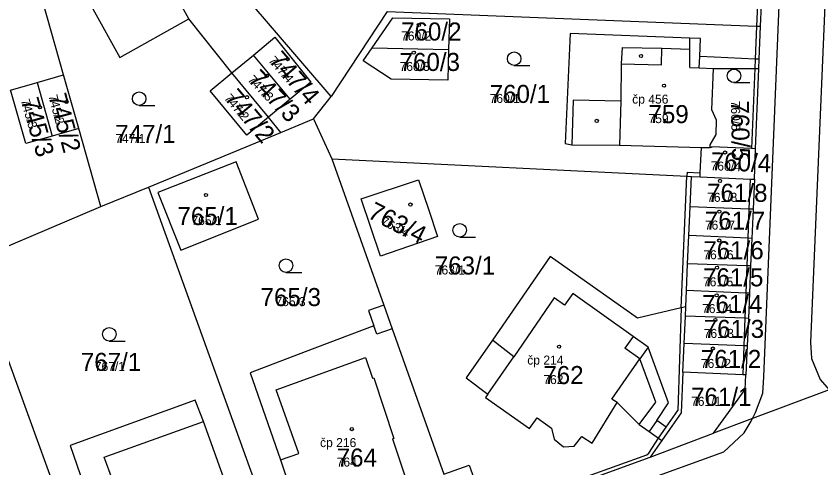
# Model space of a CAD drawing. Extents: x -763628 to -761565, y -976033 to -973833.
# Drawn here: x -762257.5 to -762168.3, y -974769.9 to -974719.9 of the extents above; entities that cross this region are included whole.
import ezdxf

# ---------------------------------------------------------------- set-up
doc = ezdxf.new("R2010")
doc.units = 0
for name, color, linetype in [('KN_cisla parcel 1000', 7, 'Continuous'), ('KN_cisla parcel 500', 7, 'Continuous'), ('KN_cisla popisna 500', 7, 'Continuous'), ('KN_hranice parcel', 7, 'Continuous'), ('KN_vnitrni kresba parcel', 7, 'Continuous'), ('KN_znacky budov', 7, 'Continuous'), ('KN_znacky kultur', 7, 'Continuous')]:
    doc.layers.add(name, color=color, linetype=linetype)

msp = doc.modelspace()

# ---------------------------------------------------------------- linework, layer by layer
at = {"layer": 'KN_hranice parcel'}
for p, q in [((-762222.55, -974728.78), (-762232.18, -974717.57)), ((-762174.98, -974721.01), (-762174.88, -974718.63)), ((-762216.37, -974719.37), (-762222.55, -974728.78)), ((-762175.13, -974724.67), (-762174.98, -974721.01)), ((-762233.58, -974726.19), (-762231.17, -974724.2)), ((-762227.11, -974729.1), (-762231.17, -974724.2)), ((-762218.03, -974723.4), (-762209.55, -974723.58)), ((-762175.17, -974725.69), (-762175.13, -974724.67)), ((-762175.55, -974734.58), (-762175.17, -974725.69)), ((-762255.15, -974727.25), (-762252.22, -974726.41)), ((-762250.53, -974732.36), (-762252.22, -974726.41)), ((-762229.52, -974731.09), (-762233.58, -974726.19)), ((-762255.15, -974727.25), (-762253.46, -974733.19)), ((-762227.11, -974729.1), (-762229.52, -974731.09)), ((-762224.51, -974731.29), (-762222.55, -974728.78)), ((-762224.51, -974731.29), (-762222.48, -974735.72)), ((-762250.53, -974732.36), (-762253.46, -974733.19)), ((-762248.08, -974741), (-762250.53, -974732.36)), ((-762181.52, -974734.45), (-762180.56, -974734.44)), ((-762175.66, -974737.97), (-762175.55, -974734.58)), ((-762222.48, -974735.72), (-762216.73, -974751.91)), ((-762182.79, -974741.03), (-762182.64, -974737.66)), ((-762182.64, -974737.66), (-762181.68, -974737.69)), ((-762175.66, -974737.97), (-762175.81, -974741.29)), ((-762248.08, -974741), (-762242.81, -974738.83)), ((-762242.81, -974738.83), (-762229.28, -974776.38)), ((-762262.34, -974747.05), (-762248.08, -974741)), ((-762182.93, -974744.19), (-762182.79, -974741.03)), ((-762176.26, -974741.27), (-762182.79, -974741.03)), ((-762175.81, -974741.29), (-762176.26, -974741.27)), ((-762175.81, -974741.29), (-762175.95, -974744.52)), ((-762183.06, -974747.32), (-762182.93, -974744.19)), ((-762176.38, -974744.5), (-762182.93, -974744.19)), ((-762175.95, -974744.52), (-762176.38, -974744.5)), ((-762175.95, -974744.52), (-762176.08, -974747.56)), ((-762183.19, -974750.28), (-762183.06, -974747.32)), ((-762176.49, -974747.55), (-762183.06, -974747.32)), ((-762176.08, -974747.56), (-762176.49, -974747.55)), ((-762176.08, -974747.56), (-762176.21, -974750.59)), ((-762183.27, -974752.09), (-762183.19, -974750.28)), ((-762176.6, -974750.57), (-762183.19, -974750.28)), ((-762176.21, -974750.59), (-762176.6, -974750.57)), ((-762176.21, -974750.59), (-762176.33, -974753.38)), ((-762183.31, -974753.13), (-762183.27, -974752.09)), ((-762183.44, -974756.17), (-762183.31, -974753.13)), ((-762176.71, -974753.37), (-762183.31, -974753.13)), ((-762176.33, -974753.38), (-762176.71, -974753.37)), ((-762176.33, -974753.38), (-762176.46, -974756.42)), ((-762183.58, -974759.34), (-762183.44, -974756.17)), ((-762176.82, -974756.41), (-762183.44, -974756.17)), ((-762176.46, -974756.42), (-762176.82, -974756.41)), ((-762176.46, -974756.42), (-762176.6, -974759.63)), ((-762187.22, -974768.75), (-762180.19, -974766.09)), ((-762185.92, -974766.91), (-762187.22, -974768.75)), ((-762205.25, -974775.28), (-762187.22, -974768.75))]:
    msp.add_line(p, q, dxfattribs=at)
for points in [[(-762252.22, -974726.41), (-762256.82, -974710.15), (-762256.94, -974709.73)], [(-762244.32, -974709.41), (-762247.53, -974711.19), (-762249.11, -974712.07), (-762251.98, -974713.67), (-762245.98, -974724.46), (-762238.32, -974720.18), (-762244.32, -974709.41)], [(-762216.37, -974719.37), (-762175.41, -974720.99), (-762174.98, -974721.01)], [(-762218.03, -974723.4), (-762215.72, -974720.07), (-762209.46, -974720.2), (-762209.55, -974723.58)], [(-762231.17, -974724.2), (-762228.8, -974722.23), (-762224.81, -974727.2), (-762227.11, -974729.1)], [(-762175.13, -974724.67), (-762175.57, -974724.65), (-762180.13, -974724.43), (-762181.72, -974724.36), (-762181.64, -974722.36), (-762182.8, -974722.32), (-762196.06, -974721.83), (-762196.64, -974734.01), (-762195.89, -974734.14), (-762190.6, -974734.19), (-762181.52, -974734.45)], [(-762209.55, -974723.58), (-762209.63, -974726.97), (-762215.92, -974726.89), (-762219.03, -974724.84), (-762218.03, -974723.4)], [(-762180.56, -974734.44), (-762180.55, -974734.17), (-762179.91, -974733.01), (-762179.85, -974731.42), (-762180.38, -974730.27), (-762180.18, -974725.68), (-762175.61, -974725.69), (-762175.17, -974725.69)], [(-762229.52, -974731.09), (-762231.9, -974733.07), (-762235.96, -974728.17), (-762233.58, -974726.19)], [(-762258.03, -974728.32), (-762258.1, -974728.08), (-762255.15, -974727.25)], [(-762253.46, -974733.19), (-762256.38, -974734.02), (-762258.03, -974728.32)], [(-762242.81, -974738.83), (-762233.69, -974735.08), (-762228.12, -974732.78), (-762224.51, -974731.29)], [(-762181.68, -974737.69), (-762181.66, -974737.25), (-762181.52, -974734.45)], [(-762175.55, -974734.58), (-762175.99, -974734.56), (-762180.41, -974734.37), (-762180.41, -974734.44), (-762180.56, -974734.44)], [(-762222.48, -974735.72), (-762183.14, -974737.64), (-762182.64, -974737.66)], [(-762241.76, -974739.42), (-762239.22, -974745.81), (-762230.6, -974742.39), (-762233.09, -974736.04), (-762241.76, -974739.42)], [(-762212.89, -974738.02), (-762211.74, -974741.39), (-762210.78, -974744.31), (-762217.1, -974746.48), (-762219.22, -974740.15), (-762212.89, -974738.02)], [(-762181.68, -974737.69), (-762176.14, -974737.95), (-762175.66, -974737.97)], [(-762183.27, -974752.09), (-762183.78, -974752.21), (-762188.63, -974753.34), (-762198.3, -974746.52), (-762204.7, -974755.79), (-762207.59, -974759.96), (-762205.19, -974761.78), (-762205.44, -974762.14), (-762200.58, -974765.58), (-762199.75, -974764.4), (-762198.13, -974765.54), (-762197.86, -974766.75), (-762196.8, -974767.63), (-762195.63, -974767.53), (-762194.79, -974766.48), (-762193.64, -974767.19), (-762190.86, -974762.69), (-762188.43, -974765.15), (-762187.32, -974765.93), (-762186.29, -974766.66), (-762185.92, -974766.91)], [(-762246.68, -974790.15), (-762246.83, -974789.73), (-762262.34, -974747.05)], [(-762216.73, -974751.91), (-762218.43, -974752.51), (-762217.83, -974754.19), (-762225.46, -974757.08), (-762231.55, -974759.4), (-762228.19, -974769.07), (-762227.02, -974772.45), (-762226.88, -974772.4), (-762226.3, -974773.96), (-762225.26, -974776.04), (-762223.36, -974781.28), (-762223.21, -974781.7)], [(-762216.73, -974751.91), (-762215.81, -974754.52), (-762210.08, -974770.65)], [(-762183.58, -974759.34), (-762183.77, -974763.86), (-762185.06, -974765.7), (-762185.92, -974766.91)], [(-762176.6, -974759.63), (-762176.94, -974759.62), (-762182.73, -974759.38), (-762183.58, -974759.34)], [(-762180.19, -974766.09), (-762176.67, -974761.26), (-762176.6, -974759.63)], [(-762164.19, -974760.11), (-762167.39, -974761.3), (-762175.87, -974764.47), (-762180.19, -974766.09)], [(-762232.15, -974777.47), (-762236.7, -974764.81), (-762237.63, -974762.46), (-762251.49, -974767.46), (-762246.28, -974782.57), (-762245.58, -974782.32), (-762243.32, -974788.46), (-762243.16, -974788.88)], [(-762210.08, -974770.65), (-762207.25, -974769.65), (-762205.4, -974774.87), (-762205.25, -974775.28)]]:
    msp.add_lwpolyline(points, dxfattribs=at)
at = {"layer": 'KN_vnitrni kresba parcel'}
for p, q in [((-762174.63, -974759.86), (-762172.19, -974701.23)), ((-762167.14, -974701.72), (-762169.44, -974756.02)), ((-762175.31, -974718.61), (-762175.41, -974720.99)), ((-762233.58, -974726.19), (-762238.32, -974720.18)), ((-762175.41, -974720.99), (-762175.57, -974724.65)), ((-762182.81, -974723.54), (-762182.8, -974722.32)), ((-762190.31, -974723.35), (-762190.41, -974725.18)), ((-762190.31, -974723.35), (-762185.92, -974723.46)), ((-762185.96, -974725.28), (-762185.92, -974723.46)), ((-762185.92, -974723.46), (-762182.81, -974723.54)), ((-762182.83, -974725.57), (-762182.81, -974723.54)), ((-762181.78, -974725.61), (-762181.72, -974724.36)), ((-762175.57, -974724.65), (-762175.61, -974725.69)), ((-762190.41, -974725.18), (-762190.46, -974729.32)), ((-762190.41, -974725.18), (-762185.96, -974725.28)), ((-762182.83, -974725.57), (-762181.78, -974725.61)), ((-762181.78, -974725.61), (-762180.18, -974725.68)), ((-762175.61, -974725.69), (-762175.99, -974734.56)), ((-762195.76, -974729.19), (-762195.89, -974734.14)), ((-762190.46, -974729.32), (-762195.76, -974729.19)), ((-762190.46, -974729.32), (-762190.6, -974734.19)), ((-762228.12, -974732.78), (-762229.52, -974731.09)), ((-762183.78, -974752.21), (-762183.14, -974737.64)), ((-762183.12, -974737.18), (-762183.14, -974737.64)), ((-762183.12, -974737.18), (-762181.66, -974737.25)), ((-762176.14, -974737.95), (-762176.26, -974741.27)), ((-762176.26, -974741.27), (-762176.38, -974744.5)), ((-762176.38, -974744.5), (-762176.49, -974747.55)), ((-762176.49, -974747.55), (-762176.6, -974750.57)), ((-762195.79, -974750.63), (-762196.72, -974751.93)), ((-762189.09, -974755.4), (-762195.79, -974750.63)), ((-762176.6, -974750.57), (-762176.71, -974753.37)), ((-762197.84, -974751.12), (-762202.33, -974757.63)), ((-762196.72, -974751.93), (-762197.84, -974751.12)), ((-762183.78, -974752.21), (-762184.14, -974763.6)), ((-762176.71, -974753.37), (-762176.82, -974756.41)), ((-762217.49, -974755.12), (-762217.83, -974754.19)), ((-762215.81, -974754.52), (-762217.49, -974755.12)), ((-762189.09, -974755.4), (-762190.01, -974756.69)), ((-762187.44, -974756.57), (-762189.09, -974755.4)), ((-762202.33, -974757.63), (-762204.7, -974755.79)), ((-762169.44, -974756.02), (-762169.32, -974757.83)), ((-762188.35, -974757.88), (-762190.01, -974756.69)), ((-762187.44, -974756.57), (-762188.35, -974757.88)), ((-762185.19, -974762.74), (-762187.44, -974756.57)), ((-762176.82, -974756.41), (-762176.94, -974759.62)), ((-762228.65, -974761.31), (-762218.74, -974757.73)), ((-762218.74, -974757.73), (-762217.98, -974760.02)), ((-762205.19, -974761.78), (-762202.33, -974757.63)), ((-762191.46, -974762.32), (-762188.35, -974757.88)), ((-762186.6, -974762.67), (-762188.35, -974757.88)), ((-762169.32, -974757.83), (-762168.39, -974760.15)), ((-762174.71, -974761.68), (-762174.63, -974759.86)), ((-762217.98, -974760.02), (-762217.84, -974759.98)), ((-762217.84, -974759.98), (-762215.61, -974766.68)), ((-762168.39, -974760.15), (-762167.39, -974761.3)), ((-762226.15, -974768.35), (-762228.65, -974761.31)), ((-762175.52, -974763.79), (-762174.71, -974761.68)), ((-762190.86, -974762.69), (-762191.46, -974762.32)), ((-762188.43, -974765.15), (-762186.6, -974762.67)), ((-762186.46, -974764.71), (-762185.19, -974762.74)), ((-762185.43, -974765.44), (-762184.14, -974763.6)), ((-762175.87, -974764.47), (-762175.52, -974763.79)), ((-762247.72, -974768.74), (-762236.7, -974764.81)), ((-762186.46, -974764.71), (-762187.32, -974765.93)), ((-762185.43, -974765.44), (-762186.46, -974764.71)), ((-762176.8, -974766.06), (-762176.02, -974764.78)), ((-762176.02, -974764.78), (-762175.87, -974764.47)), ((-762186.29, -974766.66), (-762185.43, -974765.44)), ((-762179.09, -974768.19), (-762176.8, -974766.06)), ((-762215.61, -974766.68), (-762215.75, -974766.72)), ((-762215.75, -974766.72), (-762213.88, -974772.37)), ((-762187.37, -974768.33), (-762186.29, -974766.66)), ((-762179.09, -974768.19), (-762297.57, -974811.14)), ((-762246.79, -974771.27), (-762247.72, -974768.74)), ((-762228.19, -974769.07), (-762226.15, -974768.35)), ((-762205.4, -974774.87), (-762187.59, -974768.49)), ((-762187.59, -974768.49), (-762187.37, -974768.33))]:
    msp.add_line(p, q, dxfattribs=at)
at = {"layer": 'KN_znacky budov'}
for centre in [(-762212.837, -974720.869), (-762213.407, -974723.939), (-762188.217, -974724.309), (-762227.387, -974724.659), (-762229.697, -974726.499), (-762185.677, -974727.599), (-762231.897, -974728.879), (-762251.887, -974729.399), (-762254.837, -974729.989), (-762193.127, -974731.499), (-762178.907, -974734.999), (-762179.467, -974738.149), (-762236.437, -974739.709), (-762213.777, -974740.769), (-762179.547, -974741.549), (-762179.557, -974744.749), (-762179.797, -974747.769), (-762179.837, -974750.819), (-762179.987, -974753.569), (-762197.307, -974756.509), (-762180.267, -974756.719), (-762220.267, -974765.649)]:
    msp.add_circle(centre, 0.175, dxfattribs=at)
at = {"layer": 'KN_znacky kultur'}
for p, q in [((-762202.283, -974725.36), (-762200.533, -974725.36)), ((-762177.923, -974727.26), (-762176.173, -974727.26)), ((-762243.833, -974729.79), (-762242.083, -974729.79)), ((-762208.313, -974744.37), (-762206.563, -974744.37)), ((-762227.573, -974748.28), (-762225.823, -974748.28)), ((-762247.153, -974755.89), (-762245.403, -974755.89))]:
    msp.add_line(p, q, dxfattribs=at)
for centre in [(-762202.283, -974724.61), (-762177.923, -974726.51), (-762243.833, -974729.04), (-762208.313, -974743.62), (-762227.573, -974747.53), (-762247.153, -974755.14)]:
    msp.add_circle(centre, 0.75, dxfattribs=at)

# ---------------------------------------------------------------- texts
at = {"layer": 'KN_cisla parcel 1000'}
for s, p in [('760/2', (-762214.812, -974722.595)), ('760/3', (-762214.979, -974725.968)), ('760/1', (-762205, -974729.51)), ('759', (-762187.4, -974731.75)), ('747/1', (-762246.49, -974733.94)), ('761/8', (-762180.902, -974740.469)), ('765/1', (-762239.596, -974743.04)), ('761/7', (-762181.147, -974743.544)), ('761/6', (-762181.32, -974746.829)), ('763/1', (-762211.08, -974748.52)), ('761/5', (-762181.357, -974749.831)), ('765/3', (-762230.381, -974752.02)), ('761/4', (-762181.459, -974752.792)), ('761/3', (-762181.276, -974755.545)), ('767/1', (-762250.303, -974759.2)), ('761/2', (-762181.596, -974758.871)), ('762', (-762199.05, -974760.66)), ('761/1', (-762182.68, -974763.07)), ('764', (-762221.95, -974769.8))]:
    msp.add_text(s, height=2, dxfattribs=at).set_placement(p)
for s, rotation, p in [('747/4', 311, (-762229.573, -974724.858)), ('747/3', 314, (-762231.888, -974727.007)), ('747/2', 310, (-762234.474, -974729.015)), ('745/2', 285, (-762253.907, -974728.735)), ('745/3', 286, (-762256.971, -974729.229)), ('760/5', 271, (-762178.262, -974729.264)), ('760/4', 358, (-762180.525, -974736.966)), ('763/4', 333, (-762218.643, -974742.166))]:
    msp.add_text(s, height=2, rotation=rotation, dxfattribs=at).set_placement(p)
at = {"layer": 'KN_cisla parcel 500'}
for s, p in [('760/2', (-762214.812, -974722.595)), ('760/3', (-762214.979, -974725.968)), ('760/1', (-762205, -974729.51)), ('759', (-762187.4, -974731.75)), ('747/1', (-762246.49, -974733.94)), ('761/8', (-762180.902, -974740.469)), ('765/1', (-762238.046, -974743.04)), ('761/7', (-762181.147, -974743.544)), ('761/6', (-762181.32, -974746.829)), ('763/1', (-762211.08, -974748.52)), ('761/5', (-762181.357, -974749.831)), ('765/3', (-762228.731, -974752.02)), ('761/4', (-762181.459, -974752.792)), ('761/3', (-762181.276, -974755.545)), ('767/1', (-762248.753, -974759.2)), ('761/2', (-762181.596, -974758.871)), ('762', (-762199.05, -974760.66)), ('761/1', (-762182.68, -974763.07)), ('764', (-762221.95, -974769.8))]:
    msp.add_text(s, height=1, dxfattribs=at).set_placement(p)
for s, rotation, p in [('747/4', 311, (-762229.573, -974724.858)), ('747/3', 314, (-762231.888, -974727.007)), ('745/2', 285, (-762253.907, -974728.735)), ('747/2', 310, (-762234.474, -974729.015)), ('745/3', 286, (-762256.971, -974729.229)), ('760/5', 271, (-762178.262, -974729.264)), ('760/4', 358, (-762180.525, -974736.966)), ('763/4', 333, (-762217.158, -974742.922))]:
    msp.add_text(s, height=1, rotation=rotation, dxfattribs=at).set_placement(p)
at = {"layer": 'KN_cisla popisna 500'}
for s, p in [('čp 456', (-762189.201, -974729.591)), ('čp 214', (-762200.831, -974758.501)), ('čp 216', (-762223.791, -974767.641))]:
    msp.add_text(s, height=1, dxfattribs=at).set_placement(p)

doc.saveas('drawing.dxf')
